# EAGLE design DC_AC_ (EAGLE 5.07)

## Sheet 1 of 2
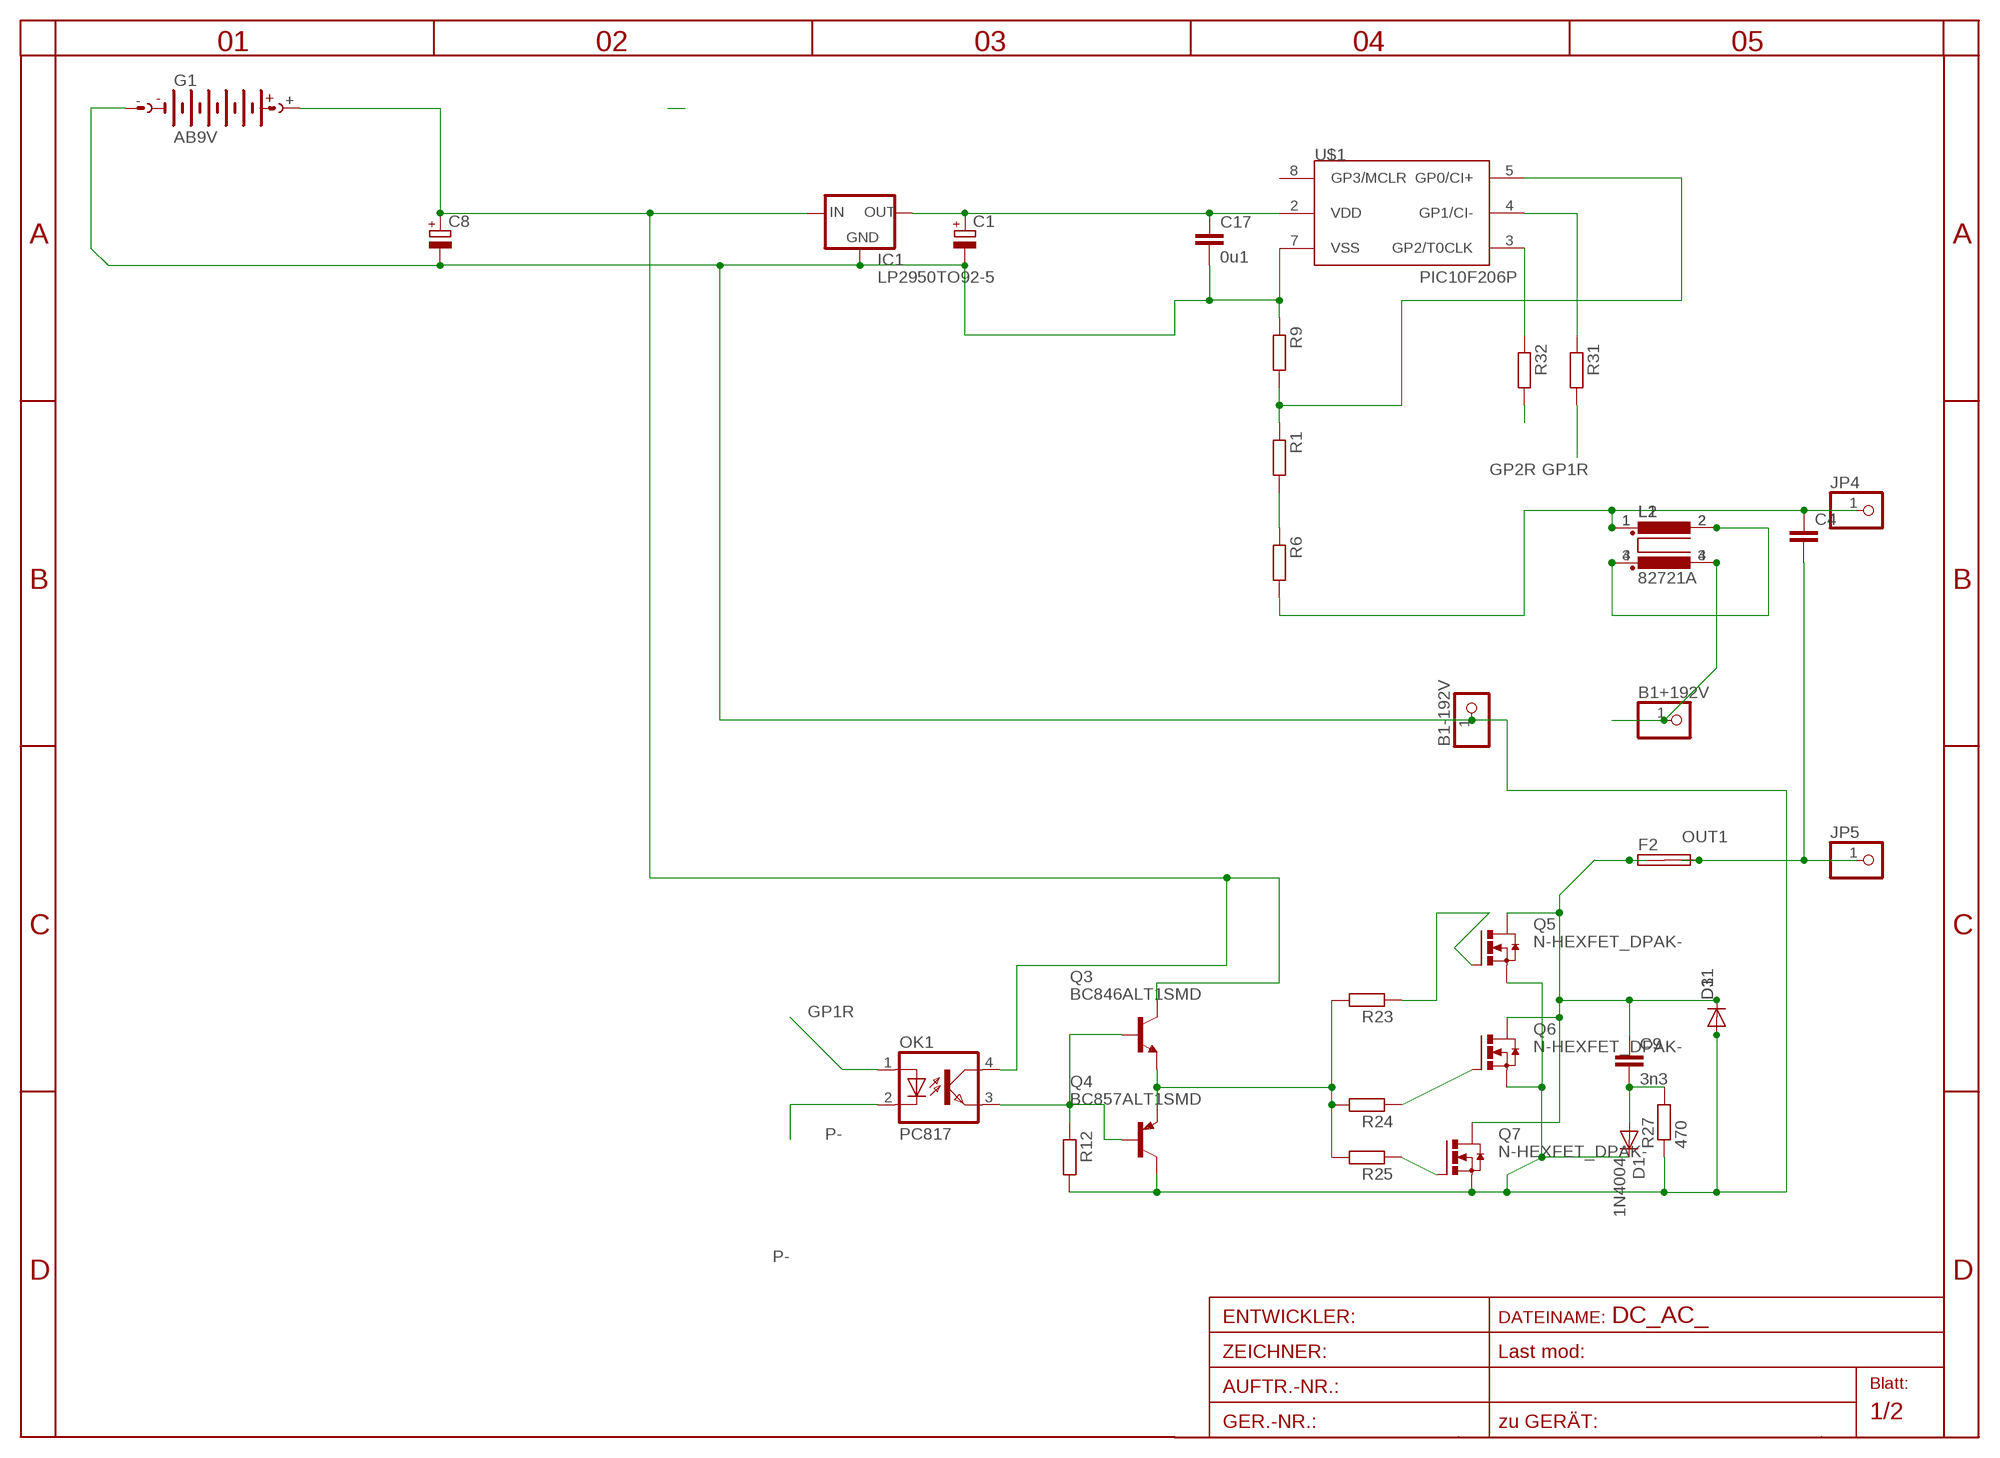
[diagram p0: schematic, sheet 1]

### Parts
B1+192V  PINHD-1X12MM3  [1X2MM3]
B1-192V  PINHD-1X12MM3  [1X2MM3]
C1  CPOL-EUE5-6  [E5-6]
C4  C-EU225-108X268  [C225-108X268]
C8  CPOL-EUE5-5  [E5-5]
C9  3n3  C-EU050-025X075  [C050-025X075]
C17  0u1  C-EUC1206  [C1206]
D1  1N4004  [DO41-10]
D3  DIODE-SMC  [SMC]
D11  DIODE-SMC  [SMC]
F2  SHK20L7MM5  [7MM5]
G1  AB9V  [AB9V]
IC1  LP2950TO92-5  [T092-5]
JP4  PINHD-1X14.5MM  [1X4MM5]
JP5  PINHD-1X14.5MM  [1X4MM5]
L1  R1405VB2  [B2]
L2  82721A  [82721A]
OK1  PC817  [DIL04]
Q3  BC846ALT1SMD  [SOT23]
Q4  BC857ALT1SMD  [SOT23-BEC]
Q5  N-HEXFET_DPAK-  [TO252]
Q6  N-HEXFET_DPAK-  [TO252]
Q7  N-HEXFET_DPAK-  [TO252]
R1  R-EU_0207/15  [0207/15]
R6  R-EU_0207/15  [0207/15]
R9  R-EU_0207/10  [0207/10]
R12  R-EU_R1206  [R1206]
R23  R-EU_0207/15  [0207/15]
R24  R-EU_0207/15  [0207/15]
R25  R-EU_0207/15  [0207/15]
R27  470  R-EU_0207/10  [0207/10]
R31  R-EU_R1206  [R1206]
R32  R-EU_R1206  [R1206]
U$1  PIC10F206P  [DIL8]

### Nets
AC1: C4.1 JP4.1 L1.1 L2.1 R6.2
BATT+: C8.+ G1.+ IC1.3(IN) OK1.4(COL) Q3.3(C)
D1: C9.1 D3.C D11.C F2.1A F2.1B Q5.3(D) Q6.3(D) Q7.3(D)
GP1R: OK1.1(A) R31.2
GP2R: R32.2 ; also sheet 2
INN: L1.2 L1.3 L2.2 L2.4
N$1: R1.1 R9.2 U$1.5(GP0/CI+)
N$3: R1.2 R6.1
N$5: C1.+ C17.1 IC1.1(OUT) U$1.2(VDD)
N$6: OK1.3(EMIT) Q3.1(B) Q4.B R12.1
N$25: Q7.1(G) R25.1
N$26: Q6.1(G) R24.1
N$27: Q5.1(G) R23.1
N$28: C9.2 D1.A R27.2
N$39: R31.1 U$1.4(GP1/CI-)
N$43: R32.1 U$1.3(GP2/T0CLK)
OUT1: C4.2 F2.2A F2.2B JP5.1 ; also sheet 2
OUT2: B1+192V.1 L1.4 L2.3 ; also sheet 2
P-: B1-192V.1 C1.- C8.- C17.2 D1.C D3.A D11.A G1.- IC1.2(GND) OK1.2(C) Q4.C Q5.2(S) Q6.2(S) Q7.2(S) R9.1 R12.2 R27.1 U$1.7(VSS) ; also sheet 2
PP1: Q3.2(E) Q4.E R23.2 R24.2 R25.2
Unconnected: U$1.8(GP3/MCLR)

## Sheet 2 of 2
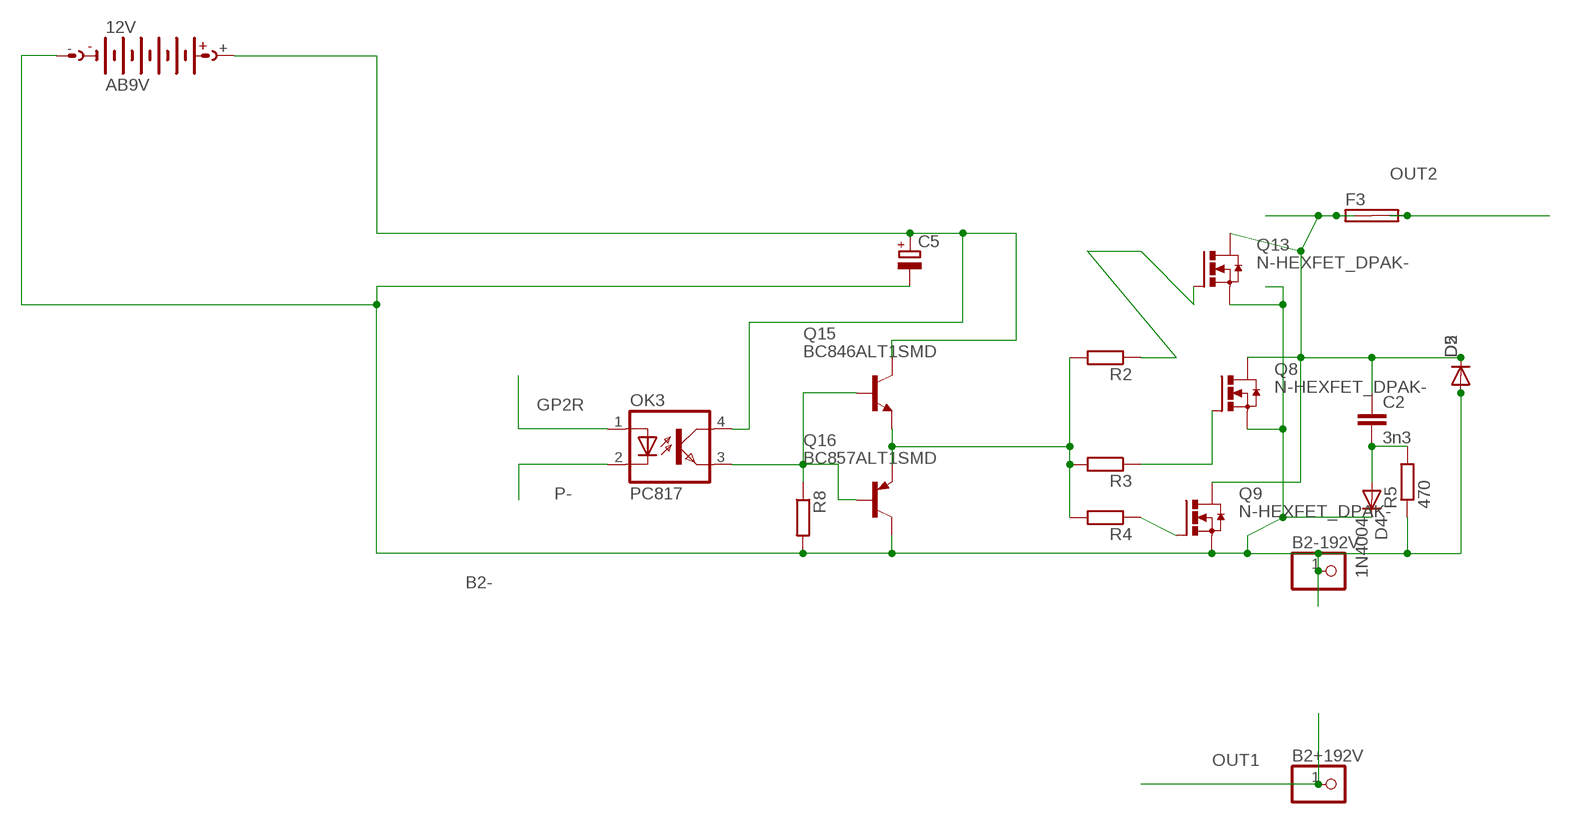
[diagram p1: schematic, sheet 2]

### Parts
12V  AB9V  [AB9V]
B2+192V  PINHD-1X12MM3  [1X2MM3]
B2-192V  PINHD-1X12MM3  [1X2MM3]
C2  3n3  C-EU050-025X075  [C050-025X075]
C5  CPOL-EUE5-6  [E5-6]
D2  DIODE-SMC  [SMC]
D4  1N4004  [DO41-10]
D5  DIODE-SMC  [SMC]
F3  SHK20L7MM5  [7MM5]
OK3  PC817  [DIL04]
Q8  N-HEXFET_DPAK-  [TO252]
Q9  N-HEXFET_DPAK-  [TO252]
Q13  N-HEXFET_DPAK-  [TO252]
Q15  BC846ALT1SMD  [SOT23]
Q16  BC857ALT1SMD  [SOT23-BEC]
R2  R-EU_0207/15  [0207/15]
R3  R-EU_0207/15  [0207/15]
R4  R-EU_0207/15  [0207/15]
R5  470  R-EU_0207/10  [0207/10]
R8  R-EU_R1206  [R1206]

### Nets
B2-: 12V.- B2-192V.1 C5.- D2.A D4.C D5.A Q8.2(S) Q9.2(S) Q13.2(S) Q16.C R5.1 R8.2
BATT+1: 12V.+ C5.+ OK3.4(COL) Q15.3(C)
D2: C2.1 D2.C D5.C F3.1A F3.1B Q8.3(D) Q9.3(D) Q13.3(D)
GP2R: OK3.1(A) ; also sheet 1
N$2: Q9.1(G) R4.1
N$10: Q8.1(G) R3.1
N$18: Q13.1(G) R2.1
N$19: C2.2 D4.A R5.2
N$21: OK3.3(EMIT) Q15.1(B) Q16.B R8.1
OUT1: B2+192V.1 ; also sheet 1
OUT2: F3.2A F3.2B ; also sheet 1
P-: OK3.2(C) ; also sheet 1
PP2: Q15.2(E) Q16.E R2.2 R3.2 R4.2

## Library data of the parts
12V G1 = battery:AB9V: 9-V BATTERY CLIP
B1+192V B1-192V B2+192V B2-192V JP4 JP5 = pinhead:PINHD-1X1: PIN HEADER
C1 C5 C8 = rcl-2:CPOL-EU: POLARIZED CAPACITOR, European symbol
C2 C9 C17 = rcl-2:C-EU: CAPACITOR, European symbol
C4 = rcl:C-EU: CAPACITOR, European symbol
D1 D4 = diode:1N4004: DIODE
D2 D3 D5 D11 = diode:DIODE-: DIODE
F2 F3 = fuse:SHK20L: FUSE HOLDER 5 x 20 mm, SH contact, SHH1 Schukat, E1073 Buerklin
IC1 = v-reg:LP2950?*: Source: http://cache.national.com/ds/LP/LP2950.pdf
L1 = inductor-nkl:R1405V: Übertrager (verlustarm) bis typ. 400kHz Power transformer (low loss) up to typ. 400kHz
L2 = inductors:82721A: FILTER
OK1 OK3 = optocoupler:PC817: SHARP OPTO COUPLER
Q3 Q15 = transistor-npn:BC846*: NPN Transistor
Q4 Q16 = transistor-pnp:BC857*: PNP Transistror
Q5-Q9 Q13 = transistor-power:N-HEXFET_?-*: HEXFET® Power MOSFET
R1-R6 R8 R9 R12 R23-R25 R27 R31 R32 = rcl-2:R-EU_: RESISTOR, European symbol
U$1 = microchip-5:PIC10F2*: uPC nW 0,25/0,5k Program Flash memory Comparator

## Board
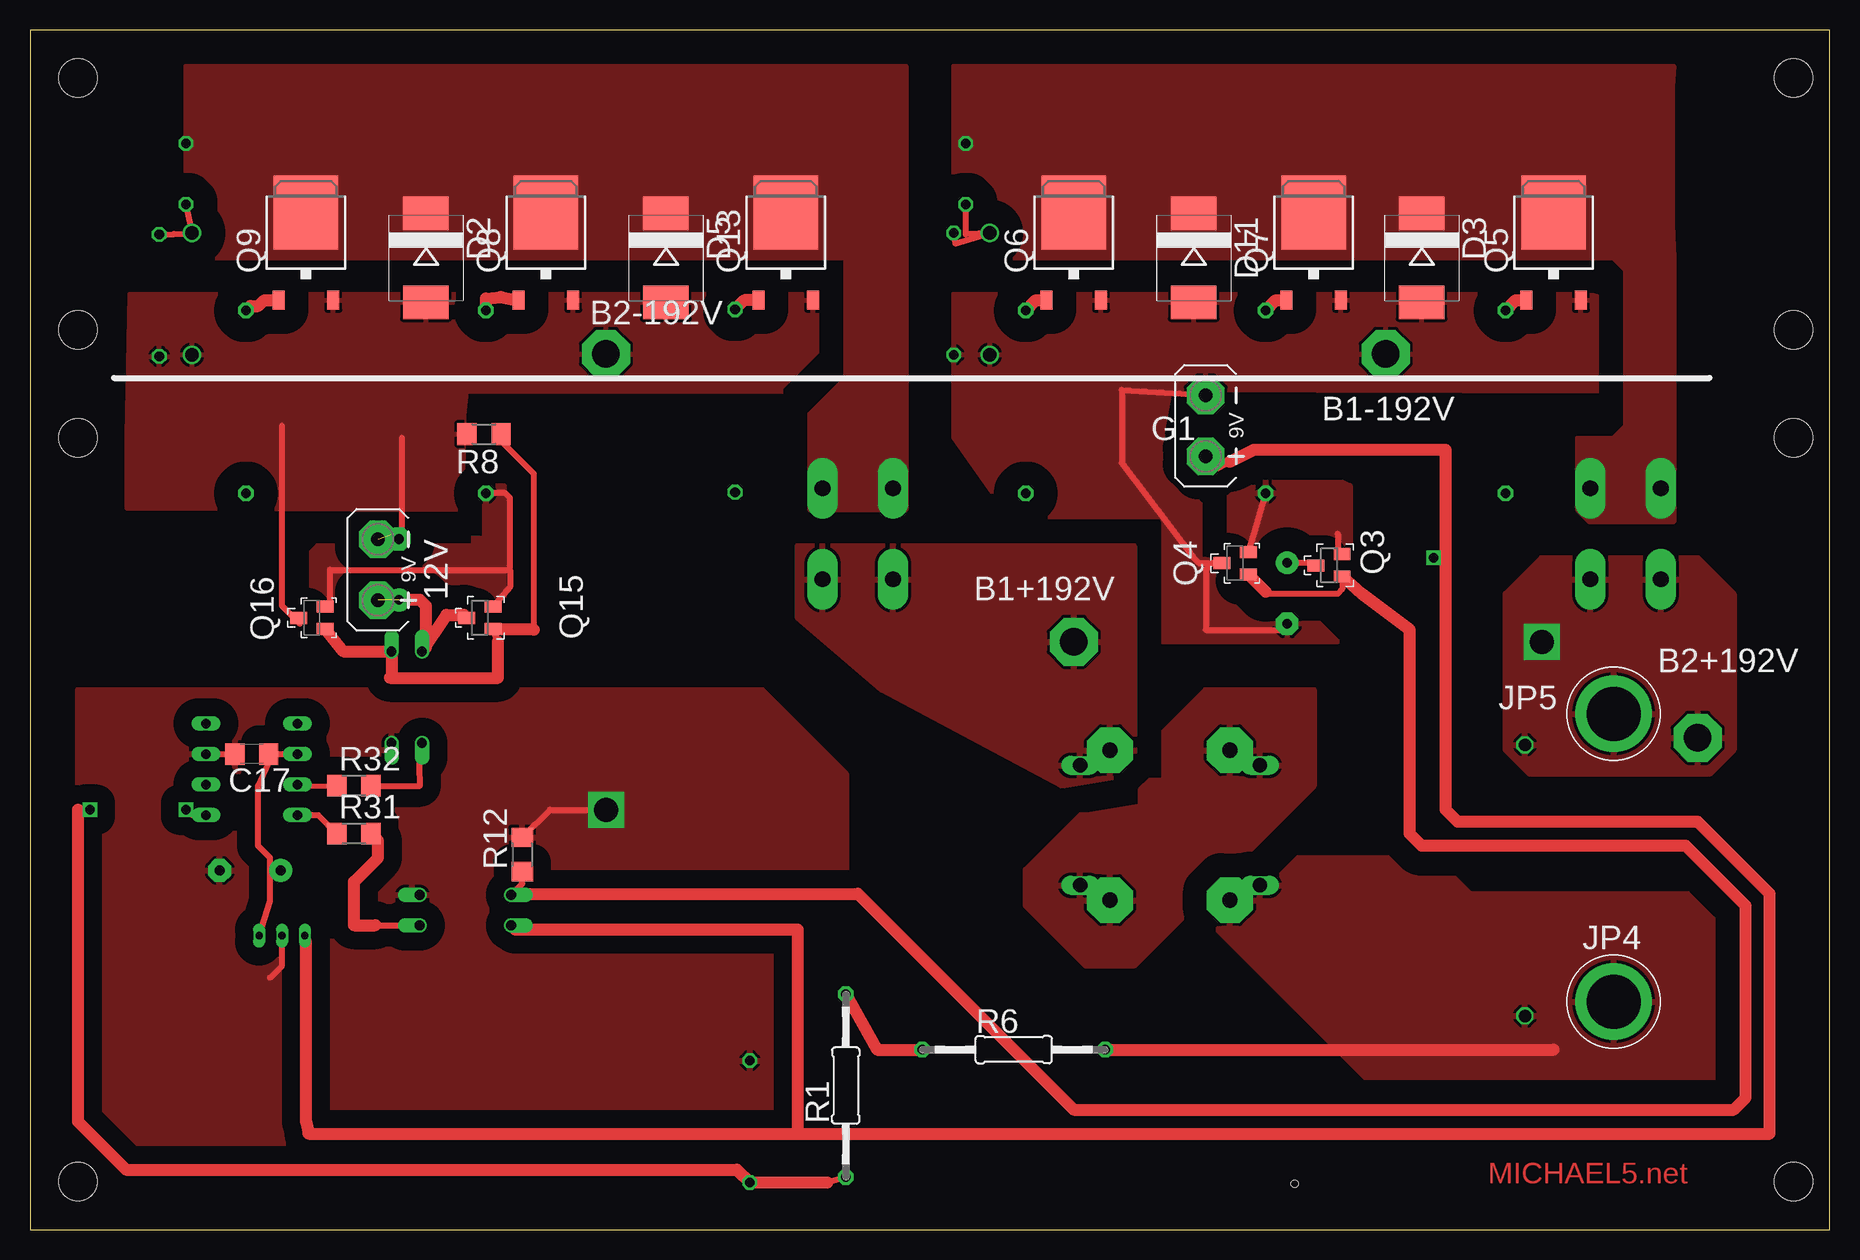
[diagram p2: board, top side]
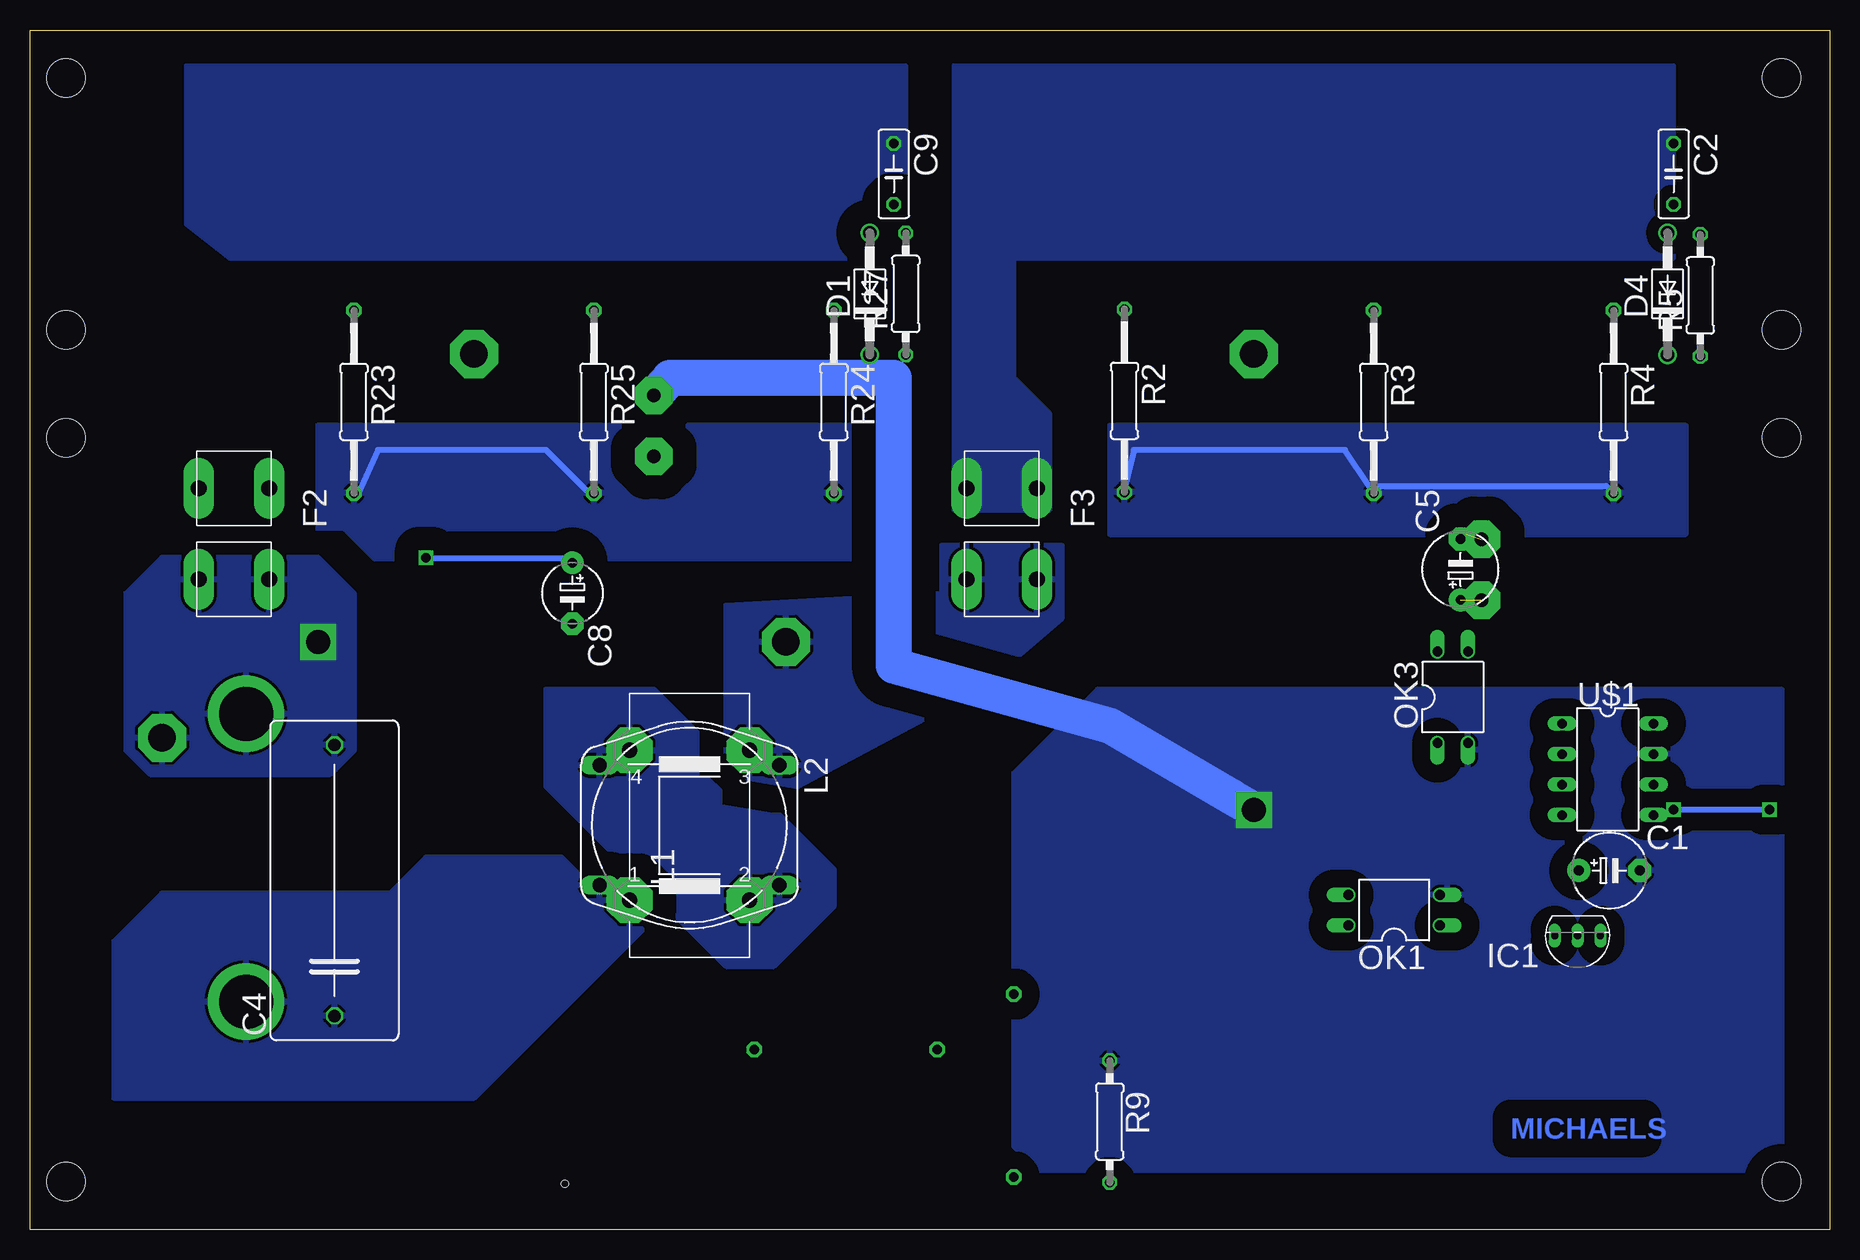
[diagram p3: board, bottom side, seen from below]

Size 150 x 100 mm. Coordinates in mm from the lower left corner, seen from the top.
Outline: 0,0 150,0 150,100 0,100 0,0
Copper layers (1*16): Top 0.035mm / dielectric 1.5mm / Bottom 0.035mm
Design rules "default *": minimum track width 12mil, minimum drill 24mil, track to track 8mil, track to pad 8mil, pad to pad 8mil, via to via 8mil, smd to smd 8mil, copper to edge 40mil, drill to drill 8mil, minimum pad ring 8mil, minimum via ring 8mil, stop-mask expansion 4mil, vias tented up to drill 0mil, thermal gap 10mil
Holes 3.2 mm at 4,96 4,4 4,75 4,66 147,96 147,4 147,75 147,66
Holes 0.6 mm at 105.41,3.81

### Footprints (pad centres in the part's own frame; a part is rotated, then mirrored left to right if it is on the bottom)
AB9V = drill 1.118 pad 3.15 octagon: + 0,2.54; - 0,-2.54
1X2MM3 = drill 2.3 pad 4 octagon: 1 0,0
E5-6 = drill 0.813 pad 1.905 round: + -2.54,0 | drill 0.813 pad 1.905 octagon: - 2.54,0
C050-025X075 = drill 0.813 octagon: 1 -2.54,0; 2 2.54,0
C225-108X268 = drill 1.016 octagon: 1 -11.303,0; 2 11.303,0
E5-5 = drill 0.813 pad 1.905 round: + -2.54,0 | drill 0.813 pad 1.905 octagon: - 2.54,0
C1206 = smd 1.6 x 1.8: 1 -1.4,0; 2 1.4,0
DO41-10 = drill 1.118 round: A 5.08,0; C -5.08,0
SMC = smd 2.8 x 3.8: A 3.7,0; C -3.7,0
7MM5 = drill 1.3 pad 2.54 long: 1A -3.8,2.94; 1B -3.8,-2.94; 2A 3.8,2.94; 2B 3.8,-2.94
T092-5 = drill 0.6 pad 0.813 long: 1 -1.905,0; 2 0,0; 3 1.905,0
1X4MM5 = drill 4.5 pad 6.35 round: 1 0,0
B2 = drill 1.27 pad 3.81 octagon: 1 -6.25,5; 2 -6.25,-5; 3 6.25,5; 4 6.25,-5
82721A = drill 1.194 long: 1 7.493,5.004; 2 -7.493,5.004; 3 -7.493,-5.004; 4 7.493,-5.004
DIL04 = drill 0.813 offset: 1 -1.27,-3.81; 2 1.27,-3.81; 3 1.27,3.81; 4 -1.27,3.81
SOT23 = smd 1 x 1.4: 1 -0.95,-1.1; 2 0.95,-1.1; 3 0,1.1
SOT23-BEC = smd 1 x 1.4: B -0.95,-1.1; C 0,1.1; E 0.95,-1.1
TO252 = smd 1 x 1.6: 1 -2.28,-3.53; 2 2.28,-3.53 | smd 5.4 x 6.2: 3 0,3.77
0207/15 = drill 0.8 pad 1.27 octagon: 1 -7.62,0; 2 7.62,0
0207/10 = drill 0.813 octagon: 1 -5.08,0; 2 5.08,0
R1206 = smd 1.6 x 1.803: 1 -1.422,0; 2 1.422,0
DIL8 = drill 0.8 long: 1 -3.81,-3.81; 2 -1.27,-3.81; 3 1.27,-3.81; 4 3.81,-3.81; 5 3.81,3.81; 6 1.27,3.81; 7 -1.27,3.81; 8 -3.81,3.81

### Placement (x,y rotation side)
12V  29,55 180 top
B1+192V  87,49 0 top
B1-192V  113,73 0 top
B2+192V  139,41 0 top
B2-192V  48,73 0 top
C1  18.35,29.93 0 bottom
C2  13,88 270 bottom
C4  124.62,29.1 90 bottom
C5  30.76,55.03 90 bottom
C8  104.8,53.05 270 bottom
C9  78,88 270 bottom
C17  18.49,39.63 180 top
D1  80,78 90 bottom
D2  33,81 270 top
D3  116,81 270 top
D4  13.5,78 90 bottom
D5  53,81 270 top
D11  97,81 270 top
F2  133,58 270 bottom
F3  69,58 270 bottom
G1  98,67 180 top
IC1  21,24.5 180 bottom
JP4  132,19 0 top
JP5  132,43 0 top
L1  95.03,33.7 90 bottom
L2  95.03,33.7 180 bottom
OK1  36.29,26.63 90 bottom
OK3  31.4,44.38 0 bottom
Q3  108.28,55.37 90 top
Q4  100.45,55.55 90 top
Q5  127,81 0 top
Q6  87,81 0 top
Q7  107,81 0 top
Q8  43,81 0 top
Q9  23,81 0 top
Q13  63,81 0 top
Q15  37.5,51 90 top
Q16  23.5,51 90 top
R1  68,12 90 top
R2  58.77,69.09 270 bottom
R3  38,69 270 bottom
R4  18,69 270 bottom
R5  10.77,77.87 90 bottom
R6  82,15 0 top
R8  37.84,66.31 180 top
R9  60,9 270 bottom
R12  41.03,31.26 90 top
R23  123,69 270 bottom
R24  83,69 270 bottom
R25  103,69 270 bottom
R27  77,78 90 bottom
R31  27,33 0 top
R32  27,37 0 top
U$1  18.49,38.36 270 bottom

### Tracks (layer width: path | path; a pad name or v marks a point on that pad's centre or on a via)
AC1
  Top 1: R6.2 127,15
  pour Top (isolate 2, rank 3): 104,31 117,31 120,28 139,28 143,24 143,11 113,11 99,25
  pour Bottom (isolate 2, rank 3): 104,31 117,31 120,28 139,28 143,24 143,11 113,11 99,25
B2-  (1 unrouted)
  Top 0.5: 31,66 31,57.81 C5.- 30.33,58 | Q16.C 22.49,50.51 21,52 21,67
  pour Top (isolate 2, rank 2): 8.35,78 64.35,78 65.62,77.47 65.62,69.85 36.36,69.85 36.15,67.85 36,60 8.09,60.12 8.09,66.2
BATT+  (via drill 0.8)
  Top 0.5: G1.+ 99,63.45 100,64 | 23,24 22.91,24.09 IC1.3 | 118,56 v117,56 | Q3.3 106.97,55.59 C8.+ | 40.46,25 OK1.4
  Top 1: 100,64 102,65 118,65 118,56 118,35 119,34 139,34 145,28 145,8 64,8 | 64,8 23.23,8 23,9 23,24 | 40.46,25 64,25 64,8
  Bottom 0.5: C8.+ 105.21,56 v117,56
BATT+1  (1 unrouted)
  Top 0.5: OK3.4 33,48.52
  Top 1: OK3.4 34.72,51.24 36.16,51.24 Q15.3 | 33,48.52 33,52 32.51,52.49 C5.+
D1
  pour Top (isolate 2, no thermals): 77,97 137,97 136.89,95.25 136.89,83.82 137,81 137,59 130,59 129,60 129,66 132,66 133,67 133,80 132,81 77,81
  pour Bottom (isolate 2, no thermals): 77,97 137,97 137,83.82 133.35,81 77,81
D2
  pour Top (isolate 2, no thermals): 13,97 73,97 73,60 65,60 65,68 68,71 68,81 13,81
  pour Bottom (isolate 1, no thermals): 13,97 73,97 73,60 65,60 65,68 68,71 68,81 13,81
GP1R
  Top 0.5: 28.78,25.36 OK1.1
  Top 1: 28.78,25.36 27,25.36 27,29 29,31 29,32.42 R31.2
GP2R
  Top 0.5: OK3.1 32.42,40.32 32.5,37 R32.2
INN
  pour Top (isolate 2, rank 2): 98,45 107,45 107,37 92,22 88,22 83,27 83,30
  pour Bottom (isolate 2, rank 2): 98,45 107,45 107,37 92,22 88,22 83,27 83,30
N$1  (via drill 0.8)
  Top 0.5: 66.46,3.92 R1.1 | 4,35 v5,35 | v13,35 13.55,34.55 U$1.5
  Top 1: 66.46,3.92 R9.2 58.92,5 8,5 4,9 4,35
  Bottom 0.5: v5,35 v13,35
N$2
  Top 1: R4.1 18.38,77 19,77 19.53,77.47 Q9.1
N$3
  Top 1: R1.2 70.62,15 R6.1
N$5
  Top 0.5: 21,29.98 20,30.05 20,31 19,32 19,37 19.89,38.89 C17.1 U$1.2 | 21,29.98 C1.+ | IC1.1 20,27.38 20,30 21.02,29.98 21,29.98
N$6
  Top 0.5: OK1.3 40.2,28 41.03,28.83 R12.1 | 103,53.15 103,53 109,53 109.38,53.38 Q3.1
  Top 1: 40.2,28 69,28 87,10 142,10 143,11 143,27 138,32 116,32 115,33 115,50 111,53 Q3.1 | 103,53.15 Q4.B
N$10
  Top 1: R3.1 38,77.62 39.25,77.75 40.53,77.47 Q8.1
N$18
  Top 1: R2.1 59.53,77.47 Q13.1
N$19
  Top 0.5: C2.2 13.47,83.34 D4.A 12,83 11.05,82.95 R5.2
N$21
  Top 0.5: 39,49 Q15.1 | 30.13,46.13 30,46 | 42,50 42,63 39.26,65.74 R8.1
  Top 1: Q16.B 26.11,48.19 OK3.3 30.13,46.13 | 39,49 39,46 30,46 | 42,50 41.95,50.05 Q15.1
N$25
  Top 1: R25.1 103.85,77.47 Q7.1
N$26
  Top 1: R24.1 83.85,77.47 Q6.1
N$27
  Top 1: R23.1 123.85,77.47 Q5.1
N$28
  Top 0.5: R27.2 77.12,82.2 D1.A 78,82.97 C9.2
N$39
  Top 0.5: R31.1 24.03,34.55 U$1.4
N$43
  Top 0.406: R32.1 22.3,37 U$1.3
OUT1  (via drill 2)
  other vias: 126,49
  pour Top (isolate 0.813): 129,56 139,56 142,53 142,40 140,38 125,38 123,40 123,53 126,56
  pour Bottom (isolate 0.813): 129,56 139,56 142,53 142,40 140,38 125,38 123,40 123,53 126,56
OUT2
  pour Top (isolate 2): 64,57 92,57 92,38 86,37 71,45 64,51
  pour Bottom (isolate 2): 64,57 74,57 74,53 92,52 92,38 86,37 71,45 64,51
P-  (via drill 2)
  Top 0.5: G1.- 91.06,69.94 91,70 91,63.9 97,56 97.45,55.55 Q4.C 98.55,55.55 98,55 98,50 104.29,50 C8.- | U$1.7 C17.2 | R12.2 43.35,35 v48,35 | IC1.2 21,22 20,21
  Bottom 0.5: v48,35 49.12,36.12 49.93,36.12
  Bottom 3: G1.- 96.66,71 78,71 78,47 60,42 49.93,36.12 v48,35
  pour Top (isolate 2, rank 2): 77,78 130,78 131.62,77.47 131.62,69.85 95,70 94.36,66.36 95.36,62.64 109,49 89,49 77,66
  pour Top (isolate 1.5, rank 3): 4,45 61,45 68,38 68,7 66,5 6,5 4,7
  pour Bottom (isolate 1.5, rank 3): 4,45 61,45 68,38 68,7 66,5 6,5 4,7
PP1
  Top 0.5: Q4.E 102,57.95 R25.2 | Q3.2 109,56.7 109,58
  Bottom 0.5: R25.2 103,61 107,65 121,65 122.62,61.38 R23.2
  pour Top (isolate 2): 100,63 108,63 110,62 110,56 101,56 100,57
  pour Bottom (isolate 2, rank 3): 80,67 126,67 126,56 79,56 79,60
PP2
  Top 0.5: Q15.2 40,53.56 40,55 | 40,55 40,61 39.62,61.38 R3.2 | Q16.E 25,51.72 25,55 40,55
  Bottom 0.5: R3.2 38.28,61.81 | 38.28,61.81 40.38,65 58,65 58.77,61.77 R2.2 | R4.2 18.62,62 38,62 38.19,61.81 38.28,61.81
  pour Top (isolate 2, rank 3): 37,62 41,62 42,61 42,52 26,52 25,51 24,51 23,52 23,56 24,57 37,57
  pour Bottom (isolate 2): 12,67 60,67 60,58 12,58 12,59

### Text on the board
Top: MICHAEL5.net
Bottom: MICHAELS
